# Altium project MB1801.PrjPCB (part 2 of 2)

## Sheet External_Debug_Interface.SchDoc: Schematic sheet title to update
size A4; Date: Not used; ApprovedBy: Not used; CheckedBy: Not used; Author: Not used; CompanyName: STMicroelectronics; DrawnBy: Not used; Engineer: Not used; Organization: Not used; Address1: Not used; Address2: Not used; Address3: Not used; Address4: Not used; DocumentNumber: Not used; Revision: Not used; SheetNumber: 7; SheetTotal: 7
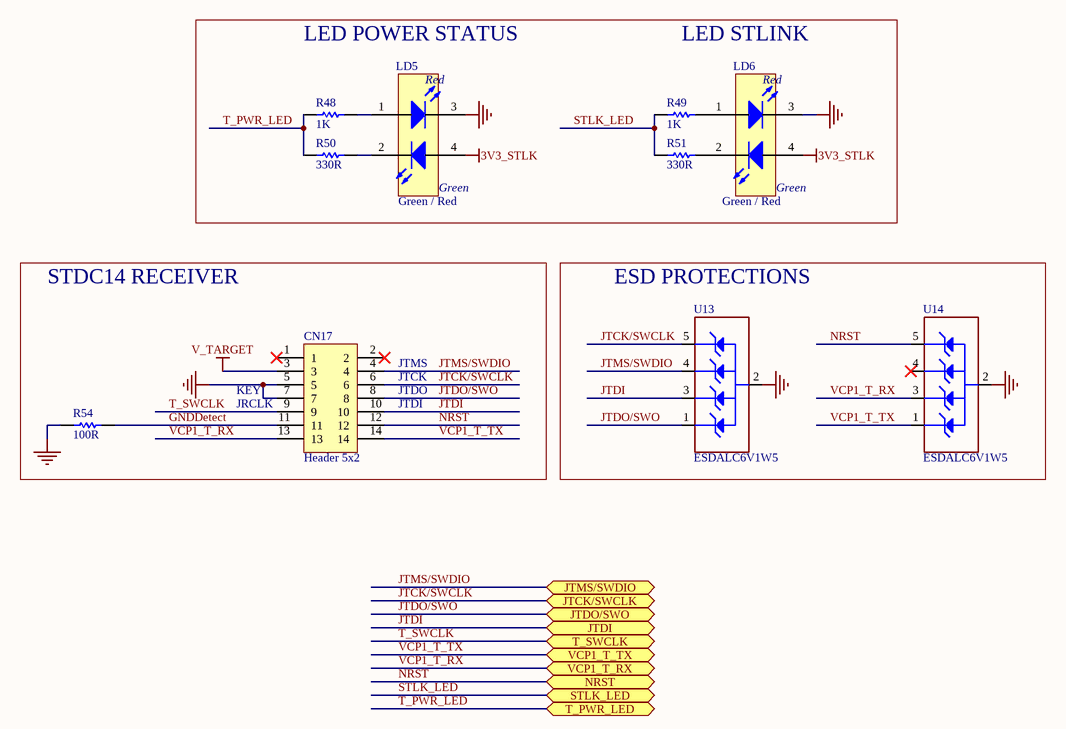
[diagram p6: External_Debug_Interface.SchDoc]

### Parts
CN17  value Header 5x2  [CON_STDC14_Receiver_MEDIUM_WITH_MIPI10_3D]  (hidden comment: Header 7x2)
LD5  value Green / Red  [LED_BI-GR_WE-150141SV73110]  (hidden comment: LED_BICOLOR)
LD6  value Green / Red  [LED_BI-GR_WE-150141SV73110]  (hidden comment: LED_BICOLOR)
R48  value 1K  [R0402]  (hidden comment: Resistor)
R49  value 1K  [R0402]  (hidden comment: Resistor)
R50  value 330R  [R0402]  (hidden comment: Resistor)
R51  value 330R  [R0402]  (hidden comment: Resistor)
R54  value 100R  [R0402]  (hidden comment: Resistor)
U13  ESDALC6V1W5  [ESD_SOT323-5L]
U14  ESDALC6V1W5  [ESD_SOT323-5L]

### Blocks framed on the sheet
STDC14 RECEIVER: CN17 R54
ESD PROTECTIONS: U13 U14

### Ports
JTCK/SWCLK (bidir), JTDI (bidir), JTDO/SWO (bidir), JTMS/SWDIO (bidir), NRST (bidir), STLK_LED (bidir), T_PWR_LED (bidir), T_SWCLK (bidir), VCP1_T_RX (bidir), VCP1_T_TX (bidir)

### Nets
3V3_STLK: LD5.4(Green_anode) LD6.4(Green_anode)
GND: CN17.5 CN17.7 LD5.3(RED_cathode) LD6.3(RED_cathode) R54.1 U13.2(GND) U14.2(GND)
V_TARGET: CN17.3
GNDDetect: CN17.11 R54.2
JTCK/SWCLK: CN17.6 U13.5(IO4) ; port JTCK/SWCLK
JTDI: CN17.10 U13.3(IO2) ; port JTDI
JTDO/SWO: CN17.8 U13.1(IO1) ; port JTDO/SWO
JTMS/SWDIO: CN17.4 U13.4(IO3) ; port JTMS/SWDIO
NRST: CN17.12 U14.5(IO4) ; port NRST
STLK_LED: R49.2 R51.1 ; port STLK_LED
T_PWR_LED: R48.2 R50.2 ; port T_PWR_LED
T_SWCLK: CN17.9 ; port T_SWCLK
VCP1_T_RX: CN17.13 U14.3(IO2) ; port VCP1_T_RX
VCP1_T_TX: CN17.14 U14.1(IO1) ; port VCP1_T_TX
NetLD5_1: LD5.1(Red_anode) R48.1
NetLD5_2: LD5.2(Green_cathode) R50.1
NetLD6_1: LD6.1(Red_anode) R49.1
NetLD6_2: LD6.2(Green_cathode) R51.2

Not connected (* = marked no-connect by the designer): CN17 1* 2*; U14 4(IO3)*

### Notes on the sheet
- LED POWER STATUS
- LED STLINK
- (near CN17) JRCLK
- (near CN17) KEY
- (near CN17) JTMS
- (near CN17) JTCK
- (near CN17) JTDO
- (near CN17) JTDI

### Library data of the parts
CN17 = MCD-01226: Header, 5x2, 1.27mm, VR, SMD, T=5.97mm/3.05mm; Part_Type: Connector; Part_Preference: Recommended; Manufacturer: SAMTEC; Manufacturer_Part_Number: FTSH-105-01-L-DV-K; Order_Code_RS: 159-2332; Component_Country_Of_Origin: China, Costa Rica, Malaysia, United States, Vietnam
LD5 LD6 = MCD-02631: LED Bicolor, Green/Red, 2V, 20mA,  4-PLCC; Part_Type: Display; Part_Preference: Recommended; Manufacturer: WURTH ELEKTRONIK; Manufacturer_Part_Number: 150141SV73110; Order_Code_RS: 184-6963
R48 R49 = MCD-02665: Resistor, 1K, 0402, +/-0.1%, 1/16W, +/-25ppm/°C; Part_Preference: Recommended; Manufacturer: YAGEO; Manufacturer_Part_Number: RT0402BRD071KL; Order_Code_RS: 199-1298
R50 R51 = MCD-00062: Resistor, 330R, 0402, +/-1%, 1/16W; Part_Preference: Recommended; Manufacturer: YAGEO; Manufacturer_Part_Number: RC0402FR-07330RL; Component_Country_Of_Origin: China
R54 = MCD-00067: Resistor, 100R, 0402, +/- 1%, 1/16W; Part_Preference: Recommended; Manufacturer: YAGEO; Manufacturer_Part_Number: RC0402FR-07100RL; Order_Code_RS: 9239111; Component_Country_Of_Origin: China; ShowFields: YES; ID: 2527
U13 U14 = MCD-00136: Dual Transil array for ESD protection; BMS_Part_Number: 9151112; Part_Type: Diode; Part_Preference: Recommended; Manufacturer: STMICROELECTRONICS; Manufacturer_HQ_COO: EU; Component_Country_Of_Origin: China

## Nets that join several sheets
3V3: Extension_CN (CN3.16 CN5.4), Accessories (SB19.2), Power_Management (C21.2 C22.2 SW1.1 U4.4)
3V3_STLK: STlink-V3EC (65 pins), External_Debug_Interface (LD5.4 LD6.4)
5V: Extension_CN (CN3.18 CN5.5), Power_Management (10 pins), STlink-V3EC (R36.2)
5V_EXT: Extension_CN (CN3.6), Power_Management (SB33.1)
5V_INT: Extension_CN (R1.2), Power_Management (C17.1 JP1.6 U3.2 U3.4)
5V_STLK: Power_Management (JP1.2), STlink-V3EC (6 pins)
5V_USB_MCU: Extension_CN (CN4.8), Accessories (6 pins), Power_Management (JP1.4)
GND: Extension_CN (46 pins), Accessories (29 pins), Power_Management (17 pins), STlink-V3EC (122 pins), External_Debug_Interface (7 pins)
V_TARGET: Extension_CN (CN1.4 CN3.12 CN5.2), Accessories (SB18.2), Power_Management (JP2.1 SW1.2), STlink-V3EC (14 pins), External_Debug_Interface (CN17.3)
VBUS_STLK: Power_Management (JP1.10), STlink-V3EC (12 pins)
VDD: Extension_CN (26 pins), Power_Management (JP2.2)
VIN: Extension_CN (CN3.24 CN5.8), Power_Management (C16.1 C18.2 SB20.2 U3.3)
B1: Extension_CN (SB2.2), Accessories (B1.2 B1.4 C12.2 U16.1)
B2: Extension_CN (SB4.2), Accessories (B2.2 B2.4 C13.2 U17.1)
B3: Extension_CN (SB6.2), Accessories (B3.2 B3.4 C14.2 U18.1)
DBG_BOOTLOADER: Extension_CN (SB28.2), STlink-V3EC (R60.1 U6.14)
JTCK/SWCLK: Extension_CN (SB15.2), STlink-V3EC (R34.2 U6.11), External_Debug_Interface (CN17.6 U13.5)
JTDI: Extension_CN (SB13.2), STlink-V3EC (R37.2), External_Debug_Interface (CN17.10 U13.3)
JTDO/SWO: Extension_CN (SB12.2), STlink-V3EC (R18.1 U6.13), External_Debug_Interface (CN17.8 U13.1)
JTMS/SWDIO: Extension_CN (SB17.2), STlink-V3EC (R35.2), External_Debug_Interface (CN17.4 U13.4)
LD1: Extension_CN (SB9.2), Accessories (LD1.2)
LD2: Extension_CN (SB10.2), Accessories (LD2.2)
LD3: Extension_CN (SB11.2), Accessories (LD3.2)
NRST: Extension_CN (SB30.2), STlink-V3EC (R29.2), External_Debug_Interface (CN17.12 U14.5)
RSTN: Extension_CN (5 pins), Accessories (B4.2 B4.4 C62.1 U19.1)
STLK_LED: STlink-V3EC (U5.D15), External_Debug_Interface (R49.2 R51.1)
T_DBG_RST: Extension_CN (SB29.2), STlink-V3EC (R2.2 U5.B2)
T_PWR_LED: STlink-V3EC (U5.H15), External_Debug_Interface (R48.2 R50.2)
T_SWCLK: STlink-V3EC (R25.1 U5.M6 U5.M11 U9.4), External_Debug_Interface (CN17.9)
USB_N: Extension_CN (SB14.2), Accessories (U1.1)
USB_P: Extension_CN (SB16.2), Accessories (U1.2)
VCP1_T_RX: Extension_CN (SB5.2), STlink-V3EC (R32.2), External_Debug_Interface (CN17.13 U14.3)
VCP1_T_TX: Extension_CN (SB3.2), STlink-V3EC (R19.1 U6.12), External_Debug_Interface (CN17.14 U14.1)
VCP2_T_CTS: Extension_CN (SB24.2 SB25.2 SB27.2), STlink-V3EC (R67.1 U15.11)
VCP2_T_RTS: Extension_CN (SB23.2 SB26.2), STlink-V3EC (R66.1 U15.12)
VCP2_T_RX: Extension_CN (SB7.2), STlink-V3EC (U15.14)
VCP2_T_TX: Extension_CN (SB8.2), STlink-V3EC (R65.1 U15.13)

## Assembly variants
USB: not fitted C12 C13 C14 C58 C59 CN10 CN11 CN14 CN16 JP3 JP4 R2 R52 R53 R60 SB19 SB20 SB22 SB24 SB26 SB27 SB28 SB29 U12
